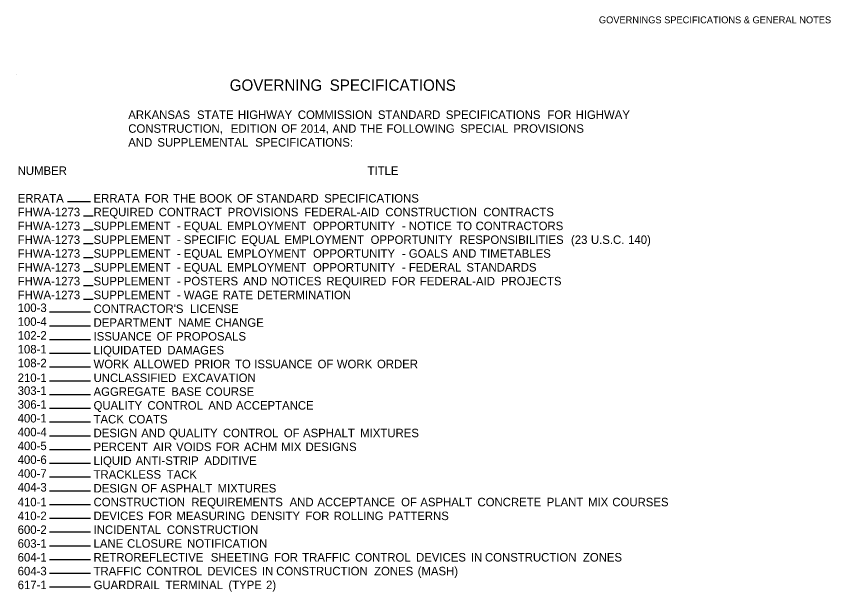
# Model space of a CAD drawing. Extents: x 1930579 to 1935779, y 596313 to 597298.
# Drawn here: x 1935089 to 1935779, y 596810 to 597298 of the extents above; entities that cross this region are included whole.
import ezdxf

# ---------------------------------------------------------------- set-up
doc = ezdxf.new("R2010")
doc.units = 0
for name, color, linetype in [('Default', 7, 'Continuous'), ('R_Border', 7, 'Continuous'), ('R_Border Prem', 7, 'Continuous')]:
    doc.layers.add(name, color=color, linetype=linetype)

msp = doc.modelspace()

# ---------------------------------------------------------------- linework, layer by layer
at = {"layer": 'R_Border'}
for p, q in [((1935088.58, 597248.45), (1935088.58, 597248.45)), ((1935131.86, 597140.77), (1935151.47, 597140.77)), ((1935145.46, 597128.7), (1935153.68, 597128.7)), ((1935145.46, 597116.9), (1935153.68, 597116.9)), ((1935145.46, 597105.1), (1935153.68, 597105.1)), ((1935145.46, 597093.31), (1935153.68, 597093.31)), ((1935145.46, 597081.51), (1935153.68, 597081.51)), ((1935145.46, 597069.71), (1935153.68, 597069.71)), ((1935145.46, 597057.91), (1935153.68, 597057.91)), ((1935116.78, 597047.17), (1935151.47, 597047.17)), ((1935116.78, 597035.52), (1935151.47, 597035.52)), ((1935116.78, 597023.87), (1935151.47, 597023.87)), ((1935116.78, 597012.22), (1935151.47, 597012.22)), ((1935116.78, 597000.57), (1935151.47, 597000.57)), ((1935116.78, 596988.93), (1935151.47, 596988.93)), ((1935116.78, 596977.28), (1935151.47, 596977.28)), ((1935116.78, 596965.63), (1935151.47, 596965.63)), ((1935116.78, 596953.98), (1935151.47, 596953.98)), ((1935116.78, 596942.34), (1935151.47, 596942.34)), ((1935116.78, 596930.69), (1935151.47, 596930.69)), ((1935116.78, 596919.04), (1935151.47, 596919.04)), ((1935116.78, 596907.39), (1935151.47, 596907.39)), ((1935116.78, 596895.74), (1935151.47, 596895.74)), ((1935116.78, 596884.1), (1935151.47, 596884.1)), ((1935116.78, 596872.45), (1935151.47, 596872.45)), ((1935116.78, 596860.8), (1935151.47, 596860.8)), ((1935116.78, 596849.15), (1935151.47, 596849.15)), ((1935116.78, 596837.5), (1935151.47, 596837.5)), ((1935116.78, 596825.86), (1935151.47, 596825.86)), ((1935116.78, 596814.21), (1935151.47, 596814.21))]:
    msp.add_line(p, q, dxfattribs=at)

# ---------------------------------------------------------------- texts
at = {"layer": 'Default'}
for s, height, p in [('GOVERNING', 9.6, (1935269.53, 597234.58)), (' SPECIFICATIONS', 9.6, (1935350.7, 597234.58)), ('           ARKANSAS', 7.2, (1935154.1, 597210.7)), (' STATE', 7.2, (1935239.1, 597210.7)), (' HIGHWAY', 7.2, (1935273.79, 597210.7)), (' COMMISSION', 7.2, (1935324.57, 597210.7)), (' STANDARD', 7.2, (1935392.49, 597210.7)), (' SPECIFICATIONS', 7.2, (1935450.09, 597210.7)), (' FOR', 7.2, (1935536.21, 597210.7)), (' HIGHWAY', 7.2, (1935560.11, 597210.7)), ('           CONSTRUCTION,', 7.2, (1935154.1, 597199)), (' EDITION', 7.2, (1935267.77, 597199)), (' OF', 7.2, (1935310.54, 597199)), (' 2014,', 7.2, (1935326.85, 597199)), (' AND', 7.2, (1935353.91, 597199)), (' THE', 7.2, (1935377.41, 597199)), (' FOLLOWING', 7.2, (1935399.79, 597199)), (' SPECIAL', 7.2, (1935462.31, 597199)), (' PROVISIONS', 7.2, (1935507.24, 597199)), ('           AND', 7.2, (1935154.1, 597187.3)), (' SUPPLEMENTAL', 7.2, (1935205.53, 597187.3)), (' SPECIFICATIONS:', 7.2, (1935288.48, 597187.3)), ('NUMBER', 7.2, (1935089.75, 597163.31)), ('TITLE', 7.2, (1935386.37, 597163.31)), ('ERRATA', 7.2, (1935089.75, 597139.91)), ('ERRATA', 7.2, (1935154.1, 597139.91)), (' FOR', 7.2, (1935194.93, 597139.91)), (' THE', 7.2, (1935218.83, 597139.91)), (' BOOK', 7.2, (1935241.2, 597139.91)), (' OF', 7.2, (1935273.05, 597139.91)), (' STANDARD', 7.2, (1935289.35, 597139.91)), (' SPECIFICATIONS', 7.2, (1935346.95, 597139.91)), ('FHWA-1273', 7.2, (1935089.75, 597128.21)), ('REQUIRED', 7.2, (1935154.1, 597128.21)), (' CONTRACT', 7.2, (1935206.67, 597128.21)), (' PROVISIONS', 7.2, (1935265.15, 597128.21)), (' FEDERAL-AID', 7.2, (1935330.04, 597128.21)), (' CONSTRUCTION', 7.2, (1935398.81, 597128.21)), (' CONTRACTS', 7.2, (1935481.83, 597128.21)), ('FHWA-1273', 7.2, (1935089.75, 597116.51)), ('SUPPLEMENT', 7.2, (1935154.1, 597116.51)), (' EQUAL', 7.2, (1935227.94, 597116.51)), (' EMPLOYMENT', 7.2, (1935264.48, 597116.51)), (' OPPORTUNITY', 7.2, (1935337.5, 597116.51)), (' NOTICE', 7.2, (1935418.72, 597116.51)), (' TO', 7.2, (1935458.98, 597116.51)), (' CONTRACTORS', 7.2, (1935475.3, 597116.51)), (' -', 7.2, (1935222.11, 597116.51)), (' -', 7.2, (1935412.89, 597116.51)), ('FHWA-1273', 7.2, (1935089.75, 597104.81)), ('SUPPLEMENT', 7.2, (1935154.1, 597104.81)), (' SPECIFIC', 7.2, (1935227.94, 597104.81)), (' EQUAL', 7.2, (1935276.73, 597104.81)), (' EMPLOYMENT', 7.2, (1935313.27, 597104.81)), (' OPPORTUNITY', 7.2, (1935386.3, 597104.81)), (' RESPONSIBILITIES', 7.2, (1935461.68, 597104.81)), (' (23', 7.2, (1935556.2, 597104.81)), (' U.S.C.', 7.2, (1935573.07, 597104.81)), (' 140)', 7.2, (1935604.61, 597104.81)), (' -', 7.2, (1935222.11, 597104.81)), ('FHWA-1273', 7.2, (1935089.75, 597093.11)), ('SUPPLEMENT', 7.2, (1935154.1, 597093.11)), (' -', 7.2, (1935222.11, 597093.11)), (' EQUAL', 7.2, (1935227.94, 597093.11)), (' EMPLOYMENT', 7.2, (1935264.48, 597093.11)), (' OPPORTUNITY', 7.2, (1935337.5, 597093.11)), (' -', 7.2, (1935412.89, 597093.11)), (' GOALS', 7.2, (1935418.72, 597093.11)), (' AND', 7.2, (1935455.65, 597093.11)), (' TIMETABLES', 7.2, (1935479.15, 597093.11)), ('FHWA-1273', 7.2, (1935089.75, 597081.41)), ('SUPPLEMENT', 7.2, (1935154.1, 597081.41)), (' EQUAL', 7.2, (1935227.94, 597081.41)), (' EMPLOYMENT', 7.2, (1935264.48, 597081.41)), (' OPPORTUNITY', 7.2, (1935337.5, 597081.41)), (' FEDERAL', 7.2, (1935418.72, 597081.41)), (' STANDARDS', 7.2, (1935467.56, 597081.41)), (' -', 7.2, (1935222.11, 597081.41)), (' -', 7.2, (1935412.89, 597081.41)), ('FHWA-1273', 7.2, (1935089.75, 597069.71)), ('SUPPLEMENT', 7.2, (1935154.1, 597069.71)), (' POSTERS', 7.2, (1935227.94, 597069.71)), (' AND', 7.2, (1935278.29, 597069.71)), (' NOTICES', 7.2, (1935301.78, 597069.71)), (' REQUIRED', 7.2, (1935348.77, 597069.71)), (' FOR', 7.2, (1935404.13, 597069.71)), (' FEDERAL-AID', 7.2, (1935428.03, 597069.71)), (' PROJECTS', 7.2, (1935496.8, 597069.71)), (' -', 7.2, (1935222.11, 597069.71)), ('FHWA-1273', 7.2, (1935089.75, 597058.01)), ('SUPPLEMENT', 7.2, (1935154.1, 597058.01)), (' -', 7.2, (1935222.11, 597058.01)), (' WAGE', 7.2, (1935227.94, 597058.01)), (' RATE', 7.2, (1935260.93, 597058.01)), (' DETERMINATION', 7.2, (1935290.02, 597058.01)), ('100-3', 7.2, (1935089.75, 597047.12)), ("CONTRACTOR'S", 7.2, (1935154.1, 597046.31)), (' LICENSE', 7.2, (1935233.19, 597046.31)), ('100-4', 7.2, (1935089.75, 597035.42)), ('DEPARTMENT', 7.2, (1935154.1, 597034.61)), (' NAME', 7.2, (1935223.22, 597034.61)), (' CHANGE', 7.2, (1935254.54, 597034.61)), ('102-2', 7.2, (1935089.75, 597023.72)), ('ISSUANCE', 7.2, (1935154.1, 597022.91)), (' OF', 7.2, (1935205, 597022.91)), (' PROPOSALS', 7.2, (1935221.31, 597022.91)), ('108-1', 7.2, (1935089.75, 597012.02)), ('LIQUIDATED', 7.2, (1935154.1, 597011.21)), (' DAMAGES', 7.2, (1935213.94, 597011.21)), ('108-2', 7.2, (1935089.75, 597000.32)), ('WORK', 7.2, (1935154.1, 596999.51)), (' ALLOWED', 7.2, (1935185.38, 596999.51)), (' PRIOR', 7.2, (1935236.83, 596999.51)), (' TO', 7.2, (1935271.34, 596999.51)), (' ISSUANCE', 7.2, (1935287.66, 596999.51)), (' OF', 7.2, (1935341.35, 596999.51)), (' WORK', 7.2, (1935357.66, 596999.51)), (' ORDER', 7.2, (1935391.72, 596999.51)), ('210-1', 7.2, (1935089.75, 596987.81)), ('UNCLASSIFIED', 7.2, (1935154.1, 596987.81)), (' EXCAVATION', 7.2, (1935226.8, 596987.81)), ('303-1', 7.2, (1935089.75, 596976.92)), ('AGGREGATE', 7.2, (1935154.1, 596976.11)), (' BASE', 7.2, (1935217.3, 596976.11)), (' COURSE', 7.2, (1935246.4, 596976.11)), ('306-1', 7.2, (1935089.75, 596965.22)), ('QUALITY', 7.2, (1935154.1, 596964.41)), (' CONTROL', 7.2, (1935197.07, 596964.41)), (' AND', 7.2, (1935248.7, 596964.41)), (' ACCEPTANCE', 7.2, (1935272.19, 596964.41)), ('400-1', 7.2, (1935089.75, 596953.52)), ('TACK', 7.2, (1935154.1, 596952.71)), (' COATS', 7.2, (1935180.92, 596952.71)), ('400-4', 7.2, (1935089.75, 596941.82)), ('DESIGN', 7.2, (1935154.1, 596941.01)), (' AND', 7.2, (1935191.85, 596941.01)), (' QUALITY', 7.2, (1935215.35, 596941.01)), (' CONTROL', 7.2, (1935261.11, 596941.01)), (' OF', 7.2, (1935312.74, 596941.01)), (' ASPHALT', 7.2, (1935329.04, 596941.01)), (' MIXTURES', 7.2, (1935377.48, 596941.01)), ('400-5', 7.2, (1935089.75, 596930.12)), ('PERCENT', 7.2, (1935154.1, 596929.31)), (' AIR', 7.2, (1935201.98, 596929.31)), (' VOIDS', 7.2, (1935221.4, 596929.31)), (' FOR', 7.2, (1935254.98, 596929.31)), (' ACHM', 7.2, (1935278.87, 596929.31)), (' MIX', 7.2, (1935310.53, 596929.31)), (' DESIGNS', 7.2, (1935331.14, 596929.31)), ('400-6', 7.2, (1935089.75, 596918.42)), ('LIQUID', 7.2, (1935154.1, 596917.61)), (' ANTI-STRIP', 7.2, (1935187.1, 596917.61)), (' ADDITIVE', 7.2, (1935245.35, 596917.61)), ('400-7', 7.2, (1935089.75, 596906.72)), ('TRACKLESS', 7.2, (1935154.1, 596905.91)), (' TACK', 7.2, (1935213.4, 596905.91)), ('404-3', 7.2, (1935089.75, 596895.02)), ('DESIGN', 7.2, (1935154.1, 596894.21)), (' OF', 7.2, (1935191.85, 596894.21)), (' ASPHALT', 7.2, (1935208.16, 596894.21)), (' MIXTURES', 7.2, (1935256.6, 596894.21)), ('410-1', 7.2, (1935089.75, 596882.51)), ('CONSTRUCTION', 7.2, (1935154.1, 596882.51)), (' REQUIREMENTS', 7.2, (1935234.32, 596882.51)), (' AND', 7.2, (1935317.64, 596882.51)), (' ACCEPTANCE', 7.2, (1935341.14, 596882.51)), (' OF', 7.2, (1935412.17, 596882.51)), (' ASPHALT', 7.2, (1935428.47, 596882.51)), (' CONCRETE', 7.2, (1935476.91, 596882.51)), (' PLANT', 7.2, (1935535.63, 596882.51)), (' MIX', 7.2, (1935570.64, 596882.51)), (' COURSES', 7.2, (1935591.26, 596882.51)), ('410-2', 7.2, (1935089.75, 596870.81)), ('DEVICES', 7.2, (1935154.1, 596870.81)), (' FOR', 7.2, (1935197.75, 596870.81)), (' MEASURING', 7.2, (1935221.64, 596870.81)), (' DENSITY', 7.2, (1935284.73, 596870.81)), (' FOR', 7.2, (1935331.06, 596870.81)), (' ROLLING', 7.2, (1935354.95, 596870.81)), (' PATTERNS', 7.2, (1935401.27, 596870.81)), ('600-2', 7.2, (1935089.75, 596859.11)), ('INCIDENTAL', 7.2, (1935154.1, 596859.11)), (' CONSTRUCTION', 7.2, (1935213.56, 596859.11)), ('603-1', 7.2, (1935089.75, 596847.41)), ('LANE', 7.2, (1935154.1, 596847.41)), (' CLOSURE', 7.2, (1935179.85, 596847.41)), (' NOTIFICATION', 7.2, (1935230.74, 596847.41)), ('604-1', 7.2, (1935089.75, 596835.71)), ('RETROREFLECTIVE', 7.2, (1935154.1, 596835.71)), (' SHEETING', 7.2, (1935250.84, 596835.71)), (' FOR', 7.2, (1935304.43, 596835.71)), (' TRAFFIC', 7.2, (1935328.32, 596835.71)), (' CONTROL', 7.2, (1935373.19, 596835.71)), (' DEVICES', 7.2, (1935424.82, 596835.71)), (' IN', 7.2, (1935471.25, 596835.71)), (' CONSTRUCTION', 7.2, (1935483.28, 596835.71)), (' ZONES', 7.2, (1935566.3, 596835.71)), ('604-3', 7.2, (1935089.75, 596824.01)), ('TRAFFIC', 7.2, (1935154.1, 596824.01)), (' CONTROL', 7.2, (1935196.18, 596824.01)), (' DEVICES', 7.2, (1935247.8, 596824.01)), (' IN', 7.2, (1935294.24, 596824.01)), (' CONSTRUCTION', 7.2, (1935306.27, 596824.01)), (' ZONES', 7.2, (1935389.28, 596824.01)), (' (MASH)', 7.2, (1935426.21, 596824.01)), ('617-1', 7.2, (1935089.75, 596812.31)), ('GUARDRAIL', 7.2, (1935154.1, 596812.31)), (' TERMINAL', 7.2, (1935212.44, 596812.31)), (' (TYPE', 7.2, (1935265.75, 596812.31)), (' 2)', 7.2, (1935297.63, 596812.31))]:
    msp.add_text(s, height=height, dxfattribs=at).set_placement(p)
at = {"layer": 'R_Border Prem'}
msp.add_text('GOVERNINGS SPECIFICATIONS & GENERAL NOTES', height=5.862, rotation=360, dxfattribs=at).set_placement((1935582.54, 597291.74))

doc.saveas('drawing.dxf')
